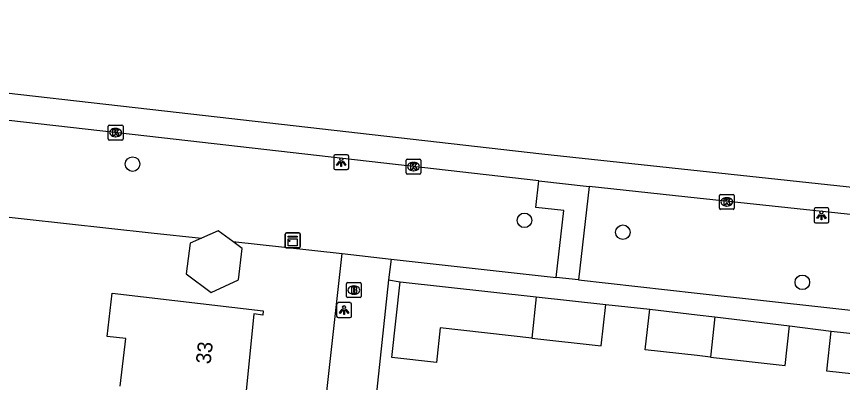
# Model space of a CAD drawing. Extents: x 162082 to 163393, y 388091 to 388632.
# Drawn here: x 162954.3 to 163009.7, y 388527.1 to 388551.7 of the extents above; entities that cross this region are included whole.
import ezdxf

# ---------------------------------------------------------------- set-up
doc = ezdxf.new("R2010")
doc.units = 0
for name, color, linetype in [('IMGEO_Boom', 7, 'Continuous'), ('IMGEO_Brandkraan', 7, 'Continuous'), ('IMGEO_Groenvoorziening', 7, 'Continuous'), ('IMGEO_Kast', 7, 'Continuous'), ('IMGEO_Kolk', 7, 'Continuous'), ('IMGEO_Lichtpunt', 7, 'Continuous'), ('IMGEO_Pand', 7, 'Continuous'), ('IMGEO_Pand_nummerreeks', 7, 'Continuous'), ('IMGEO_Rijbaan_lokaal_gesloten', 7, 'Continuous'), ('IMGEO_Voetpad_open', 7, 'Continuous')]:
    doc.layers.add(name, color=color, linetype=linetype)

msp = doc.modelspace()

# ---------------------------------------------------------------- linework, layer by layer
at = {"layer": 'IMGEO_Boom'}
for centre in [(162962.093, 388541.802), (162988.399, 388538.024), (162995.001, 388537.226), (163007.046, 388533.862)]:
    msp.add_circle(centre, 0.489, dxfattribs=at)
at = {"layer": 'IMGEO_Brandkraan'}
for p, q in [((162976.445, 388532.918), (162976.445, 388533.77)), ((162976.52, 388533.844), (162977.372, 388533.844)), ((162977.446, 388533.77), (162977.446, 388532.918)), ((162976.933, 388533.624), (162976.958, 388533.624)), ((162977.372, 388532.844), (162976.52, 388532.844)), ((162976.956, 388533.064), (162976.931, 388533.064))]:
    msp.add_line(p, q, dxfattribs=at)
for points in [[(162976.445, 388532.918), (162976.445, 388533.77)], [(162976.52, 388533.844), (162977.372, 388533.844)], [(162977.446, 388533.77), (162977.446, 388532.918)], [(162976.793, 388533.544), (162976.793, 388533.144), (162977.006, 388533.144)], [(162977.024, 388533.544), (162976.793, 388533.544)], [(162976.972, 388533.463), (162976.918, 388533.463), (162976.918, 388533.387)], [(162976.918, 388533.387), (162976.971, 388533.387)], [(162976.98, 388533.311), (162976.918, 388533.311), (162976.918, 388533.23)], [(162976.918, 388533.23), (162976.98, 388533.23)], [(162977.372, 388532.844), (162976.52, 388532.844)]]:
    msp.add_lwpolyline(points, dxfattribs=at)
for centre, radius, start, end in [((162976.522, 388533.768), 0.0765, 91.552, 178.448), ((162976.522, 388533.768), 0.0765, 91.552, 178.448), ((162977.37, 388533.768), 0.0765, 1.552, 88.448), ((162977.37, 388533.768), 0.0765, 1.552, 88.448), ((162976.973, 388533.425), 0.0379, 267.8285, 90.9355), ((162976.981, 388533.27), 0.0404, 269.8759, 90.5077), ((162977.012, 388533.395), 0.251, 268.6676, 293.5347), ((162977.028, 388533.399), 0.145, 59.4692, 91.5367), ((162977.053, 388533.446), 0.0922, 285.5137, 58.1501), ((162977.058, 388533.254), 0.105, 301.3115, 78.989), ((162976.522, 388532.92), 0.0765, 181.552, 268.448), ((162976.522, 388532.92), 0.0765, 181.552, 268.448), ((162977.37, 388532.92), 0.0765, 271.552, 358.448), ((162977.37, 388532.92), 0.0765, 271.552, 358.448)]:
    msp.add_arc(centre, radius, start, end, dxfattribs=at)
for centre, major_axis, ratio, start_param, end_param in [((162976.932, 388533.344), (-0.387, 0.002), 0.722429, 4.712389, 7.853982), ((162976.957, 388533.344), (-0.39, 0.002), 0.717154, 1.570796, 4.712389)]:
    msp.add_ellipse(centre, major_axis=major_axis, ratio=ratio, start_param=start_param, end_param=end_param, dxfattribs=at)
at = {"layer": 'IMGEO_Groenvoorziening'}
for points in [[(162951.947, 388538.443), (162963.34, 388537.196), (162966.716, 388536.827)], [(162968.813, 388536.597), (162972.29, 388536.217), (162976.166, 388535.793)]]:
    msp.add_lwpolyline(points, dxfattribs=at)
at = {"layer": 'IMGEO_Kast'}
for p, q in [((162972.342, 388536.253), (162972.342, 388537.094)), ((162972.342, 388537.094), (162972.342, 388536.253)), ((162972.417, 388537.178), (162973.258, 388537.178)), ((162973.258, 388537.178), (162972.417, 388537.178)), ((162973.342, 388537.103), (162973.342, 388536.262)), ((162973.342, 388536.262), (162973.342, 388537.103)), ((162973.267, 388536.178), (162972.426, 388536.178)), ((162972.426, 388536.178), (162973.267, 388536.178))]:
    msp.add_line(p, q, dxfattribs=at)
for points in [[(162972.537, 388536.968), (162973.137, 388536.968), (162973.137, 388536.883), (162972.537, 388536.883), (162972.537, 388536.968)], [(162972.537, 388536.793), (162973.137, 388536.793), (162973.137, 388536.304), (162972.537, 388536.304), (162972.537, 388536.793)]]:
    msp.add_lwpolyline(points, dxfattribs=at)
msp.add_circle((162972.621, 388536.642), 0.0377, dxfattribs=at)
for centre, start, end in [((162972.42, 388537.1), 92.4484, 184.2845), ((162972.42, 388537.1), 92.4484, 184.2845), ((162973.264, 388537.1), 2.4484, 94.2845), ((162973.264, 388537.1), 2.4484, 94.2845), ((162972.42, 388536.256), 182.4484, 274.2845), ((162972.42, 388536.256), 182.4484, 274.2845), ((162973.264, 388536.256), 272.4484, 4.2845), ((162973.264, 388536.256), 272.4484, 4.2845)]:
    msp.add_arc(centre, 0.0779, start, end, dxfattribs=at)
at = {"layer": 'IMGEO_Kolk'}
for p, q in [((162960.454, 388543.488), (162960.454, 388544.34)), ((162960.529, 388544.414), (162961.381, 388544.414)), ((162960.942, 388544.194), (162960.967, 388544.194)), ((162961.455, 388544.34), (162961.455, 388543.488)), ((162960.965, 388543.634), (162960.94, 388543.634)), ((162961.381, 388543.414), (162960.529, 388543.414)), ((162980.448, 388541.208), (162980.448, 388542.06)), ((162980.523, 388542.134), (162981.375, 388542.134)), ((162981.449, 388542.06), (162981.449, 388541.208)), ((162980.936, 388541.914), (162980.961, 388541.914)), ((162981.375, 388541.134), (162980.523, 388541.134)), ((162980.959, 388541.354), (162980.934, 388541.354)), ((163001.553, 388539.763), (163002.405, 388539.763)), ((163001.478, 388538.837), (163001.478, 388539.689)), ((163001.966, 388539.543), (163001.991, 388539.543)), ((163002.479, 388539.689), (163002.479, 388538.837)), ((163002.405, 388538.763), (163001.553, 388538.763)), ((163001.989, 388538.983), (163001.964, 388538.983))]:
    msp.add_line(p, q, dxfattribs=at)
for points in [[(162960.454, 388543.488), (162960.454, 388544.34)], [(162960.529, 388544.414), (162961.381, 388544.414)], [(162961.455, 388544.34), (162961.455, 388543.488)], [(162960.775, 388544.114), (162960.898, 388544.114), (162960.898, 388543.963), (162961.028, 388544.114), (162961.192, 388544.114), (162961.046, 388543.963), (162961.199, 388543.714), (162961.047, 388543.714), (162960.962, 388543.878), (162960.898, 388543.811), (162960.898, 388543.714), (162960.775, 388543.714), (162960.775, 388544.114)], [(162961.381, 388543.414), (162960.529, 388543.414)], [(162980.448, 388541.208), (162980.448, 388542.06)], [(162980.523, 388542.134), (162981.375, 388542.134)], [(162981.449, 388542.06), (162981.449, 388541.208)], [(162980.769, 388541.834), (162980.892, 388541.834), (162980.892, 388541.683), (162981.022, 388541.834), (162981.186, 388541.834), (162981.04, 388541.683), (162981.193, 388541.434), (162981.041, 388541.434), (162980.956, 388541.598), (162980.892, 388541.531), (162980.892, 388541.434), (162980.769, 388541.434), (162980.769, 388541.834)], [(162981.375, 388541.134), (162980.523, 388541.134)], [(163001.553, 388539.763), (163002.405, 388539.763)], [(163001.478, 388538.837), (163001.478, 388539.689)], [(163001.799, 388539.463), (163001.922, 388539.463), (163001.922, 388539.312), (163002.052, 388539.463), (163002.216, 388539.463), (163002.07, 388539.312), (163002.223, 388539.063), (163002.071, 388539.063), (163001.986, 388539.227), (163001.922, 388539.16), (163001.922, 388539.063), (163001.799, 388539.063), (163001.799, 388539.463)], [(163002.479, 388539.689), (163002.479, 388538.837)], [(163002.405, 388538.763), (163001.553, 388538.763)]]:
    msp.add_lwpolyline(points, dxfattribs=at)
for centre, start, end in [((162960.531, 388544.338), 91.552, 178.448), ((162960.531, 388544.338), 91.552, 178.448), ((162961.379, 388544.338), 1.552, 88.448), ((162961.379, 388544.338), 1.552, 88.448), ((162960.531, 388543.49), 181.552, 268.448), ((162960.531, 388543.49), 181.552, 268.448), ((162961.379, 388543.49), 271.552, 358.448), ((162961.379, 388543.49), 271.552, 358.448), ((162980.525, 388542.058), 91.552, 178.448), ((162980.525, 388542.058), 91.552, 178.448), ((162981.373, 388542.058), 1.552, 88.448), ((162981.373, 388542.058), 1.552, 88.448), ((162980.525, 388541.21), 181.552, 268.448), ((162980.525, 388541.21), 181.552, 268.448), ((162981.373, 388541.21), 271.552, 358.448), ((162981.373, 388541.21), 271.552, 358.448), ((163001.555, 388539.687), 91.552, 178.448), ((163001.555, 388539.687), 91.552, 178.448), ((163002.403, 388539.687), 1.552, 88.448), ((163002.403, 388539.687), 1.552, 88.448), ((163001.555, 388538.839), 181.552, 268.448), ((163001.555, 388538.839), 181.552, 268.448), ((163002.403, 388538.839), 271.552, 358.448), ((163002.403, 388538.839), 271.552, 358.448)]:
    msp.add_arc(centre, 0.0765, start, end, dxfattribs=at)
for centre, major_axis, ratio, start_param, end_param in [((162960.941, 388543.914), (-0.387, 0.002), 0.722429, 4.712389, 7.853982), ((162960.966, 388543.914), (-0.39, 0.002), 0.717154, 1.570796, 4.712389), ((162980.935, 388541.634), (-0.387, 0.002), 0.722429, 4.712389, 7.853982), ((162980.96, 388541.634), (-0.39, 0.002), 0.717154, 1.570796, 4.712389), ((163001.965, 388539.263), (-0.387, 0.002), 0.722429, 4.712389, 7.853982), ((163001.99, 388539.263), (-0.39, 0.002), 0.717154, 1.570796, 4.712389)]:
    msp.add_ellipse(centre, major_axis=major_axis, ratio=ratio, start_param=start_param, end_param=end_param, dxfattribs=at)
at = {"layer": 'IMGEO_Lichtpunt'}
for p, q in [((162975.603, 388542.334), (162975.603, 388541.527)), ((162975.603, 388542.334), (162975.603, 388541.527)), ((162976.505, 388542.429), (162975.697, 388542.429)), ((162976.505, 388542.429), (162975.697, 388542.429)), ((162976.599, 388541.527), (162976.599, 388542.334)), ((162976.599, 388541.527), (162976.599, 388542.334)), ((162975.697, 388541.433), (162976.505, 388541.433)), ((162975.697, 388541.433), (162976.505, 388541.433)), ((163007.835, 388538.763), (163007.835, 388537.956)), ((163007.835, 388538.763), (163007.835, 388537.956)), ((163008.737, 388538.858), (163007.929, 388538.858)), ((163008.737, 388538.858), (163007.929, 388538.858)), ((163008.831, 388537.956), (163008.831, 388538.763)), ((163008.831, 388537.956), (163008.831, 388538.763)), ((163007.929, 388537.862), (163008.737, 388537.862)), ((163007.929, 388537.862), (163008.737, 388537.862)), ((162975.791, 388532.402), (162975.791, 388531.595)), ((162975.791, 388532.402), (162975.791, 388531.595)), ((162976.693, 388532.497), (162975.885, 388532.497)), ((162976.693, 388532.497), (162975.885, 388532.497)), ((162976.787, 388531.595), (162976.787, 388532.402)), ((162976.787, 388531.595), (162976.787, 388532.402)), ((162975.885, 388531.501), (162976.693, 388531.501)), ((162975.885, 388531.501), (162976.693, 388531.501))]:
    msp.add_line(p, q, dxfattribs=at)
for points in [[(162975.977, 388541.998), (162976.016, 388541.97), (162975.828, 388541.708), (162975.79, 388541.735), (162975.977, 388541.998)], [(162976.189, 388541.97), (162976.227, 388541.997), (162976.414, 388541.735), (162976.375, 388541.707), (162976.189, 388541.97)], [(162976.079, 388541.95), (162976.126, 388541.95), (162976.126, 388541.628), (162976.079, 388541.628), (162976.079, 388541.95)], [(163008.209, 388538.427), (163008.248, 388538.399), (163008.06, 388538.137), (163008.022, 388538.164), (163008.209, 388538.427)], [(163008.311, 388538.379), (163008.358, 388538.379), (163008.358, 388538.057), (163008.311, 388538.057), (163008.311, 388538.379)], [(163008.421, 388538.399), (163008.459, 388538.426), (163008.646, 388538.164), (163008.607, 388538.136), (163008.421, 388538.399)], [(162976.165, 388532.066), (162976.204, 388532.038), (162976.016, 388531.776), (162975.978, 388531.803), (162976.165, 388532.066)], [(162976.267, 388532.018), (162976.314, 388532.018), (162976.314, 388531.696), (162976.267, 388531.696), (162976.267, 388532.018)], [(162976.377, 388532.038), (162976.415, 388532.065), (162976.602, 388531.803), (162976.563, 388531.775), (162976.377, 388532.038)]]:
    msp.add_lwpolyline(points, dxfattribs=at)
for centre in [(162976.102, 388542.132), (163008.334, 388538.561), (162976.29, 388532.2)]:
    msp.add_circle(centre, 0.0994, dxfattribs=at)
for centre, start, end in [((162975.697, 388542.334), 90, 180), ((162975.697, 388542.334), 90, 180), ((162976.505, 388542.334), 0, 90), ((162976.505, 388542.334), 0, 90), ((162975.697, 388541.527), 180, 270), ((162975.697, 388541.527), 180, 270), ((162976.505, 388541.527), 270, 0), ((162976.505, 388541.527), 270, 360), ((163007.929, 388538.763), 90, 180), ((163007.929, 388538.763), 90, 180), ((163008.737, 388538.763), 0, 90), ((163008.737, 388538.763), 0, 90), ((163007.929, 388537.956), 180, 270), ((163007.929, 388537.956), 180, 270), ((163008.737, 388537.956), 270, 0), ((163008.737, 388537.956), 270, 360), ((162975.885, 388532.402), 90, 180), ((162975.885, 388532.402), 90, 180), ((162976.693, 388532.402), 0, 90), ((162976.693, 388532.402), 0, 90), ((162975.885, 388531.595), 180, 270), ((162975.885, 388531.595), 180, 270), ((162976.693, 388531.595), 270, 0), ((162976.693, 388531.595), 270, 360)]:
    msp.add_arc(centre, 0.0946, start, end, dxfattribs=at)
at = {"layer": 'IMGEO_Pand'}
for points in [[(162968.813, 388536.597), (162967.84, 388537.318), (162966.716, 388536.827)], [(162966.716, 388536.827), (162965.968, 388536.5), (162965.7, 388534.425), (162967.375, 388533.179), (162969.195, 388534.028), (162969.44, 388536.133), (162968.813, 388536.597)], [(162988.889, 388530.12), (162982.746, 388530.798), (162982.491, 388528.49), (162979.494, 388528.822), (162980.054, 388533.894)], [(162980.054, 388533.894), (162989.194, 388532.884)], [(162961.259, 388526.881), (162961.635, 388530.082), (162960.379, 388530.23), (162960.721, 388533.142), (162970.868, 388531.951), (162970.826, 388531.664), (162970.239, 388531.758), (162969.672, 388526.125), (162970.174, 388526.078), (162970.149, 388525.878)], [(162989.194, 388532.884), (162988.889, 388530.12)], [(162989.194, 388532.884), (162993.863, 388532.368)], [(162988.889, 388530.12), (162993.557, 388529.604), (162993.863, 388532.368)], [(163000.888, 388528.842), (163000, 388528.942), (162996.503, 388529.335), (162996.805, 388532.066)], [(162996.805, 388532.066), (163000, 388531.683), (163001.186, 388531.541)], [(163001.186, 388531.541), (163000.888, 388528.842)], [(163001.186, 388531.541), (163006.194, 388530.941)], [(163000.888, 388528.842), (163005.901, 388528.28), (163006.194, 388530.941)], [(163013.233, 388527.395), (163008.697, 388527.895), (163008.994, 388530.588)], [(163008.994, 388530.588), (163013.531, 388530.088)]]:
    msp.add_lwpolyline(points, dxfattribs=at)
at = {"layer": 'IMGEO_Rijbaan_lokaal_gesloten'}
for points in [[(162908.609, 388551.708), (162949.636, 388547.042), (162964.238, 388545.381), (162989.572, 388542.5), (163000.195, 388541.342), (163031.254, 388538.019), (163031.947, 388537.937), (163069.626, 388533.478), (163131.386, 388526.936), (163144.801, 388525.515), (163163.528, 388523.377)], [(162989.365, 388540.682), (162964.031, 388543.563), (162919.873, 388548.585), (162914.4, 388549.207)], [(162989.365, 388540.682), (162992.744, 388540.298)], [(163156.391, 388522.352), (163145.834, 388523.559), (163144.608, 388523.695), (163069.433, 388531.658), (163031.039, 388536.202), (163000, 388539.522), (162992.744, 388540.298)]]:
    msp.add_lwpolyline(points, dxfattribs=at)
at = {"layer": 'IMGEO_Voetpad_open'}
for points in [[(162990.531, 388534.189), (162991.041, 388538.679), (162989.163, 388538.892), (162989.365, 388540.682)], [(162992.744, 388540.298), (162992.032, 388534.021)], [(162973.287, 388510.017), (162976.166, 388535.793)], [(162976.166, 388535.793), (162979.457, 388535.426)], [(162979.457, 388535.426), (162979.264, 388534.02)], [(162979.457, 388535.426), (162990.531, 388534.189)], [(162979.264, 388534.02), (162976.669, 388509.646)], [(162979.264, 388534.02), (162980.054, 388533.894)], [(162992.032, 388534.021), (162990.531, 388534.189)], [(162992.032, 388534.021), (163000, 388533.142), (163155.658, 388515.929)], [(162993.863, 388532.368), (162996.805, 388532.066)], [(163006.194, 388530.941), (163008.994, 388530.588)]]:
    msp.add_lwpolyline(points, dxfattribs=at)

# ---------------------------------------------------------------- texts
at = {"layer": 'IMGEO_Pand_nummerreeks'}
msp.add_text('33', height=1, rotation=83.6983, dxfattribs=at).set_placement((162967.324, 388528.341))

doc.saveas('drawing.dxf')
